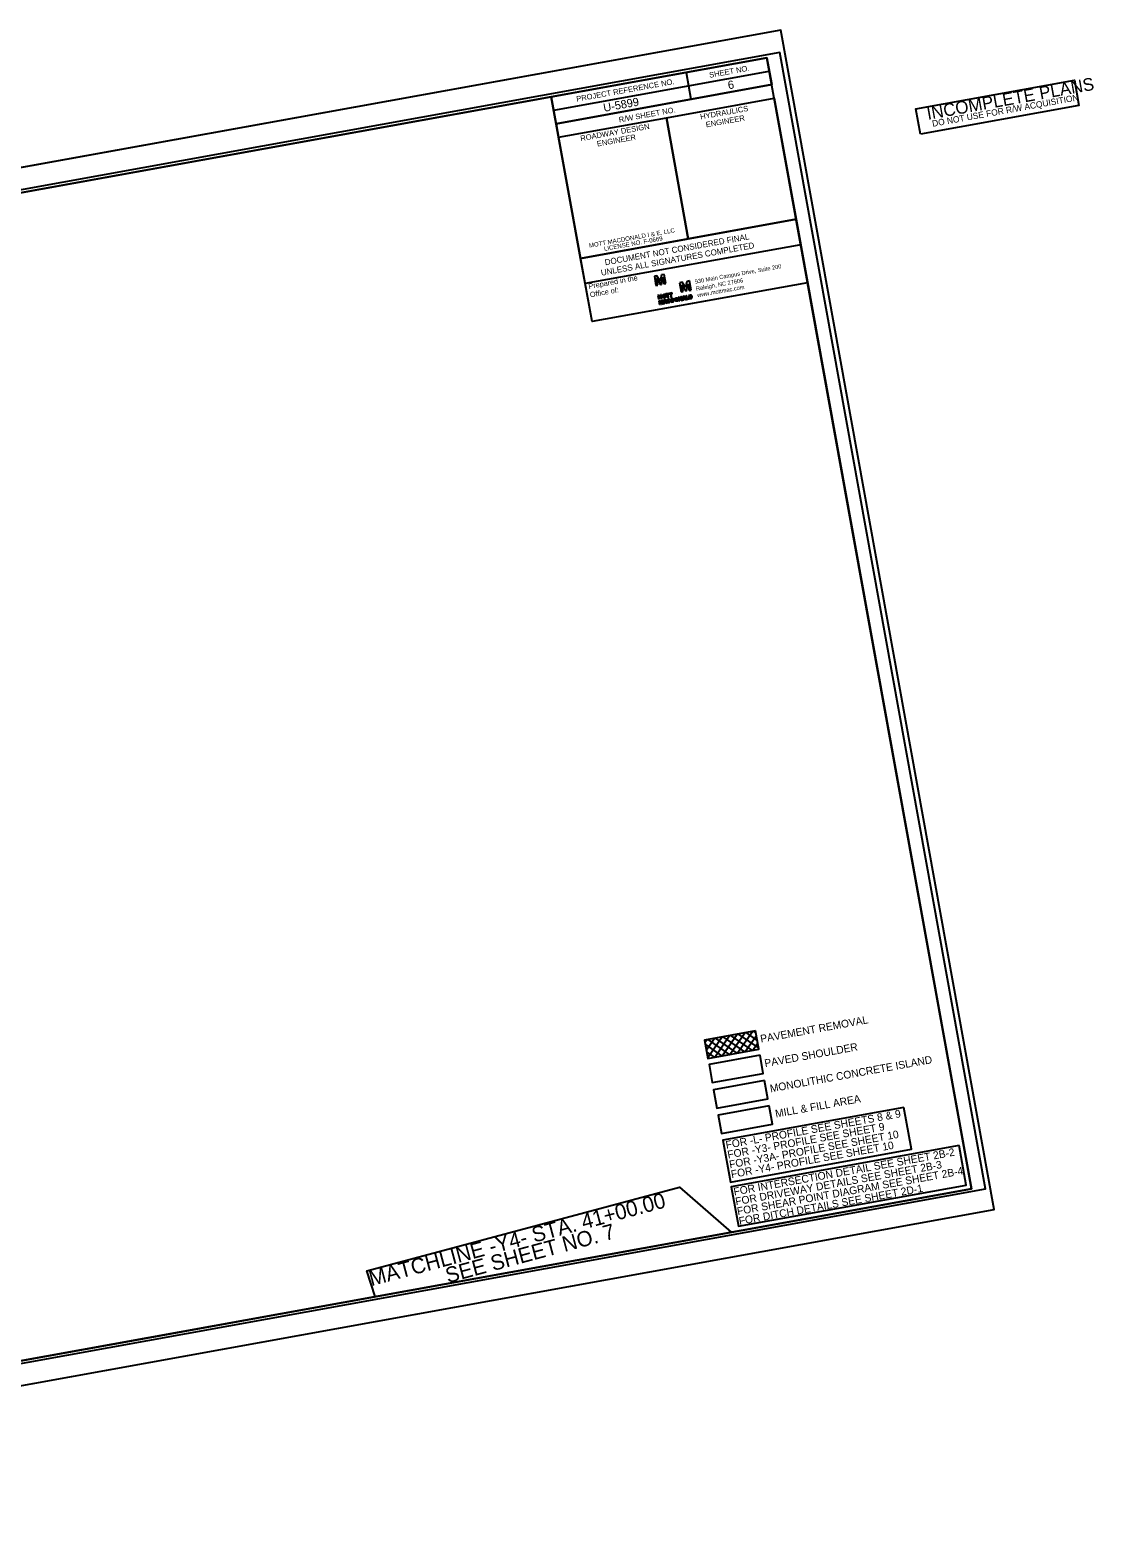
# Model space of a CAD drawing. Extents: x 1620188 to 1622130, y 897586 to 898964.
# Drawn here: x 1621159 to 1622130, y 897586 to 898964 of the extents above; entities that cross this region are included whole.
import ezdxf

# ---------------------------------------------------------------- set-up
doc = ezdxf.new("R2010")
doc.units = 0
for name, color, linetype in [('Matchline', 7, 'Continuous'), ('Matchline Text', 7, 'Continuous'), ('Old_Level_2', 7, 'Continuous'), ('Old_Level_40', 7, 'Continuous'), ('Old_Level_42', 7, 'Continuous'), ('Old_Level_45', 7, 'Continuous'), ('Prop DSN Text', 7, 'Continuous'), ('Prop Rem of Exist Asph Pvmt', 7, 'Continuous'), ('Prop Shade Light', 7, 'Continuous'), ('Sheet Cutting Line CELL', 7, 'Continuous'), ('Sheet Data Field CELL', 7, 'Continuous'), ('Sheet Layout Plan Border', 7, 'Continuous'), ('Sheet Plan CELL', 7, 'Continuous'), ('Sheet Plot Border Inside CELL', 7, 'Continuous'), ('Sheet Plot Border Outside CELL', 7, 'Continuous'), ('Sheet Sticker Exception Certification CELL', 7, 'Continuous'), ('Sheet Sticker Incomplete CELL', 7, 'Continuous')]:
    doc.layers.add(name, color=color, linetype=linetype)

msp = doc.modelspace()

# ---------------------------------------------------------------- linework, layer by layer
at = {"layer": 'Matchline'}
msp.add_line((1621466.5, 897830.2), (1621752, 897906.6), dxfattribs=at)
at = {"layer": 'Old_Level_2'}
for p, q in [((1621731.5, 898739.3), (1621729.1, 898738.9)), ((1621729.1, 898738.9), (1621730.6, 898730.5)), ((1621731.2, 898736.8), (1621731.3, 898736.9)), ((1621732.3, 898730.8), (1621731.2, 898736.8)), ((1621731.3, 898736.9), (1621734.7, 898731.3)), ((1621734.5, 898734.5), (1621731.5, 898739.3)), ((1621735.6, 898740.1), (1621734.5, 898734.5)), ((1621734.5, 898734.5), (1621734.6, 898734.5)), ((1621734.6, 898734.5), (1621734.5, 898734.4)), ((1621734.5, 898734.4), (1621734.5, 898734.5)), ((1621735.5, 898731.4), (1621736.7, 898737.9)), ((1621738.1, 898740.5), (1621735.6, 898740.1)), ((1621736.7, 898737.9), (1621736.8, 898737.9)), ((1621736.8, 898737.9), (1621737.9, 898731.8)), ((1621739.6, 898732.2), (1621738.1, 898740.5)), ((1621754.6, 898733.4), (1621752.1, 898733)), ((1621752.1, 898733), (1621753.6, 898724.6)), ((1621757.5, 898728.6), (1621754.6, 898733.4)), ((1621758.7, 898734.2), (1621757.6, 898728.6)), ((1621761.1, 898734.6), (1621758.7, 898734.2)), ((1621762.7, 898726.3), (1621761.1, 898734.6)), ((1621730.6, 898730.5), (1621732.3, 898730.8)), ((1621733.2, 898721.5), (1621732.2, 898721.4)), ((1621732.2, 898721.4), (1621732.8, 898718.2)), ((1621733.5, 898718.3), (1621733.1, 898720.6)), ((1621733.1, 898720.6), (1621733.1, 898720.6)), ((1621733.1, 898720.6), (1621734.4, 898718.4)), ((1621734.3, 898719.7), (1621733.2, 898721.5)), ((1621734.8, 898721.8), (1621734.3, 898719.7)), ((1621734.7, 898731.3), (1621735.5, 898731.4)), ((1621734.7, 898718.5), (1621735.2, 898721)), ((1621735.7, 898722), (1621734.8, 898721.8)), ((1621735.2, 898721), (1621735.2, 898721)), ((1621735.2, 898721), (1621735.6, 898718.7)), ((1621735.6, 898718.7), (1621736.3, 898718.8)), ((1621736.3, 898718.8), (1621735.7, 898722)), ((1621737.9, 898731.8), (1621739.6, 898732.2)), ((1621745.3, 898718.6), (1621743.8, 898718.3)), ((1621745.9, 898722.9), (1621746, 898722.9)), ((1621748, 898723.3), (1621748.1, 898723.3)), ((1621748, 898723.3), (1621748.1, 898723.3)), ((1621753.6, 898724.6), (1621755.4, 898724.9)), ((1621754.3, 898730.9), (1621754.3, 898731)), ((1621754.3, 898731), (1621757.7, 898725.4)), ((1621755.4, 898724.9), (1621754.3, 898730.9)), ((1621757.6, 898728.6), (1621757.5, 898728.6)), ((1621757.5, 898728.6), (1621757.5, 898728.6)), ((1621757.6, 898728.6), (1621757.6, 898728.6)), ((1621757.7, 898725.4), (1621758.5, 898725.5)), ((1621758.5, 898725.5), (1621759.8, 898732)), ((1621759.8, 898732), (1621759.8, 898732)), ((1621759.8, 898732), (1621760.9, 898725.9)), ((1621761.9, 898721.6), (1621760.4, 898721.3)), ((1621760.4, 898721.3), (1621760.4, 898721.3)), ((1621760.4, 898721.3), (1621760.7, 898719.7)), ((1621760.7, 898719.7), (1621761, 898718.1)), ((1621760.9, 898725.9), (1621762.7, 898726.3)), ((1621761.2, 898720.9), (1621762, 898721)), ((1621761.5, 898718.9), (1621761.2, 898720.9)), ((1621762.3, 898719), (1621761.5, 898718.9)), ((1621762, 898721), (1621762, 898721)), ((1621732.8, 898718.2), (1621733.5, 898718.3)), ((1621734.1, 898716.6), (1621733.1, 898716.4)), ((1621733.1, 898716.4), (1621733.7, 898713.2)), ((1621733.7, 898713.2), (1621734.4, 898713.3)), ((1621734.4, 898713.3), (1621734, 898715.6)), ((1621734, 898715.6), (1621734, 898715.6)), ((1621734, 898715.6), (1621735.3, 898713.5)), ((1621735.2, 898714.7), (1621734.1, 898716.6)), ((1621734.4, 898718.4), (1621734.7, 898718.5)), ((1621735.7, 898716.9), (1621735.2, 898714.7)), ((1621735.3, 898713.5), (1621735.6, 898713.5)), ((1621735.6, 898713.5), (1621736.1, 898716)), ((1621736.6, 898717), (1621735.7, 898716.9)), ((1621736.1, 898716), (1621736.1, 898716)), ((1621736.1, 898716), (1621736.5, 898713.7)), ((1621736.5, 898713.7), (1621737.2, 898713.8)), ((1621737.2, 898713.8), (1621736.6, 898717)), ((1621743, 898717.1), (1621743.5, 898717.5)), ((1621743.8, 898715.7), (1621743.2, 898715.9)), ((1621743.8, 898718.3), (1621744.1, 898716.7)), ((1621744.1, 898716.7), (1621744.4, 898715.1)), ((1621744.4, 898715.1), (1621745.9, 898715.4)), ((1621744.6, 898717.9), (1621745.4, 898718)), ((1621745, 898715.9), (1621744.6, 898717.9)), ((1621745.8, 898716), (1621745, 898715.9)), ((1621761, 898718.1), (1621762.4, 898718.4))]:
    msp.add_line(p, q, dxfattribs=at)
for points in [[(1621739.8, 898722.1), (1621740.7, 898722.3), (1621741.2, 898719.7), (1621741.9, 898719.8), (1621741.4, 898722.4), (1621742.4, 898722.6), (1621742.3, 898723.2), (1621739.7, 898722.7), (1621739.8, 898722.1)], [(1621742.8, 898722.7), (1621743.7, 898722.8), (1621744.2, 898720.2), (1621744.9, 898720.3), (1621744.4, 898722.9), (1621745.3, 898723.1), (1621745.2, 898723.7), (1621742.7, 898723.2), (1621742.8, 898722.7)], [(1621751.9, 898718.6), (1621751.9, 898718.6), (1621753.8, 898716.8), (1621754.4, 898717), (1621753.9, 898720.1), (1621753.2, 898720), (1621753.6, 898718), (1621751.7, 898719.8), (1621751, 898719.6), (1621751.6, 898716.4), (1621752.2, 898716.6), (1621751.9, 898718.6)], [(1621754.9, 898717), (1621755.6, 898717.2), (1621755.7, 898717.7), (1621757.1, 898718), (1621757.4, 898717.5), (1621758.2, 898717.6), (1621756.3, 898720.6), (1621755.5, 898720.4), (1621754.9, 898717)], [(1621755.8, 898718.4), (1621756.1, 898719.8), (1621756.8, 898718.5), (1621755.8, 898718.4)], [(1621760.6, 898718.1), (1621760.5, 898718.6), (1621759.1, 898718.4), (1621758.6, 898721), (1621758, 898720.9), (1621758.5, 898717.7), (1621760.6, 898718.1)], [(1621737.6, 898713.9), (1621738.3, 898714), (1621738.4, 898714.6), (1621739.8, 898714.9), (1621740.1, 898714.4), (1621740.9, 898714.5), (1621739.1, 898717.5), (1621738.2, 898717.3), (1621737.6, 898713.9)], [(1621738.5, 898715.2), (1621738.8, 898716.7), (1621739.5, 898715.4), (1621738.5, 898715.2)]]:
    msp.add_lwpolyline(points, dxfattribs=at)
msp.add_arc((1621762.1, 898720), 1.62, 280.2583, 100.2583, dxfattribs=at)
for centre, major_axis, ratio in [((1621738.2, 898720.8), (-0.29, 1.6), 0.993118), ((1621738.2, 898720.8), (-0.19, 1.04), 0.916103), ((1621749.2, 898717.6), (-0.29, 1.6), 0.993118), ((1621749.2, 898717.6), (-0.19, 1.04), 0.916103)]:
    msp.add_ellipse(centre, major_axis=major_axis, ratio=ratio, dxfattribs=at)
for centre, major_axis, ratio, start_param, end_param in [((1621745.6, 898717), (0.29, -1.6), 0.930276, 0, 3.141593), ((1621762.1, 898720), (0.181, -0.998), 0.900832, 0, 3.141593), ((1621742.3, 898716.4), (-0.29, 1.6), 0.993118, 5.246647, 10.366427), ((1621742.3, 898716.4), (-0.19, 1.04), 0.916103, 5.276876, 10.296021), ((1621745.6, 898717), (0.181, -0.998), 0.900832, 0, 3.141593)]:
    msp.add_ellipse(centre, major_axis=major_axis, ratio=ratio, start_param=start_param, end_param=end_param, dxfattribs=at)
at = {"layer": 'Old_Level_40'}
for points in [[(1621821.6, 898049.5), (1621775, 898041.1), (1621778, 898024.4), (1621824.6, 898032.8)], [(1621825.6, 898027.3), (1621779, 898018.8), (1621782, 898002.2), (1621828.6, 898010.6)], [(1621829.8, 898004.1), (1621783.2, 897995.7), (1621786.2, 897979), (1621832.8, 897987.4)], [(1621834, 897980.9), (1621787.4, 897972.5), (1621790.4, 897955.8), (1621837, 897964.2)], [(1621957, 897979.5), (1621791.6, 897949.6), (1621798.5, 897911.3), (1621963.9, 897941.3)], [(1622007.4, 897944.8), (1621799.2, 897907.1), (1621805.8, 897871), (1622013.9, 897908.7)]]:
    msp.add_lwpolyline(points, close=True, dxfattribs=at)
at = {"layer": 'Old_Level_42'}
msp.add_lwpolyline([(1621869, 898733), (1621672.2, 898697.4), (1621665.9, 898732.1)], dxfattribs=at)
at = {"layer": 'Prop Rem of Exist Asph Pvmt'}
for p, q in [((1621777.9, 898025.2), (1621790.8, 898043.9)), ((1621784.2, 898025.5), (1621797.8, 898045.2)), ((1621791.1, 898026.8), (1621804.8, 898046.5)), ((1621791.7, 898044.1), (1621811.4, 898030.4)), ((1621798.1, 898028), (1621811.7, 898047.7)), ((1621798.7, 898045.4), (1621818.4, 898031.7)), ((1621805, 898029.3), (1621818.7, 898049)), ((1621805.6, 898046.6), (1621824.4, 898033.6)), ((1621812, 898030.6), (1621822.3, 898045.4)), ((1621812.6, 898047.9), (1621823.2, 898040.5)), ((1621819.5, 898049.1), (1621821.9, 898047.5)), ((1621775.3, 898039.1), (1621776.9, 898041.4)), ((1621775.7, 898036.9), (1621790.5, 898026.7)), ((1621776.6, 898032.2), (1621783.9, 898042.7)), ((1621777, 898030), (1621783.6, 898025.4)), ((1621777.8, 898041.6), (1621797.5, 898027.9)), ((1621784.7, 898042.8), (1621804.4, 898029.2)), ((1621818.9, 898031.8), (1621823.6, 898038.5))]:
    msp.add_line(p, q, dxfattribs=at)
at = {"layer": 'Prop Shade Light'}
for points in [[(1621825.6, 898027.3), (1621779, 898018.8), (1621782, 898002.2), (1621828.6, 898010.6), (1621825.6, 898027.3)], [(1621829.8, 898004.1), (1621783.2, 897995.7), (1621786.2, 897979), (1621832.8, 897987.4), (1621829.8, 898004.1)], [(1621834, 897980.9), (1621787.4, 897972.5), (1621790.4, 897955.8), (1621837, 897964.2), (1621834, 897980.9)]]:
    msp.add_lwpolyline(points, dxfattribs=at)
at = {"layer": 'Sheet Cutting Line CELL'}
for p, q in [((1621844.5, 898963.7), (1620187.9, 898663.9)), ((1620382.9, 897586.4), (1622039.5, 897886.2))]:
    msp.add_line(p, q, dxfattribs=at)
at = {"layer": 'Sheet Layout Plan Border'}
msp.add_lwpolyline([(1620396.1, 898448.3), (1620511.7, 898448.3), (1620511.8, 898225.2), (1620537.8, 897924.1), (1620549.3, 897792), (1620711.8, 897792), (1620711.8, 897668.8), (1621290.7, 897773.5), (1621387.6, 897791.1), (1621474.2, 897806.7), (1621466.5, 897830.2), (1621752, 897906.6), (1621799.3, 897865.6), (1622018.8, 897905.3), (1621899.5, 898564.6), (1621869, 898733), (1621765.3, 898714.2), (1621672.2, 898697.4), (1621635, 898902.9), (1620355.8, 898671.4)], close=True, dxfattribs=at)
at = {"layer": 'Sheet Plan CELL'}
for p, q in [((1621637.2, 898890.6), (1621834, 898926.2)), ((1621639.4, 898878.2), (1621836.3, 898913.9)), ((1621639.4, 898878.2), (1621836.3, 898913.9)), ((1621758, 898925.1), (1621762.5, 898900.5)), ((1621639.4, 898878.2), (1621641.6, 898865.9)), ((1621740.1, 898883.7), (1621760.1, 898773.1))]:
    msp.add_line(p, q, dxfattribs=at)
for points in [[(1621831.8, 898938.5), (1620355.8, 898671.4), (1620542.8, 897638.2), (1622018.8, 897905.3)], [(1621634.9, 898902.9), (1621831.8, 898938.5), (1621836.3, 898913.9), (1621639.4, 898878.2)], [(1620542.8, 897638.2), (1620355.7, 898671.4), (1621634.9, 898902.9), (1621661.7, 898755.2), (1621858.5, 898790.9), (1622018.8, 897905.3)], [(1621740.1, 898883.7), (1621838.5, 898901.6), (1621858.5, 898790.9), (1621760.1, 898773)], [(1621641.6, 898865.9), (1621740.1, 898883.7), (1621760.1, 898773), (1621661.7, 898755.2)]]:
    msp.add_lwpolyline(points, close=True, dxfattribs=at)
at = {"layer": 'Sheet Plot Border Inside CELL'}
msp.add_lwpolyline([(1620392.2, 897608.4), (1622031.5, 897905.1), (1621843.7, 898943.2), (1620204.3, 898646.5)], close=True, dxfattribs=at)
at = {"layer": 'Sheet Plot Border Outside CELL'}
msp.add_lwpolyline([(1620382.9, 897586.4), (1622039.5, 897886.2), (1621844.5, 898963.7), (1620187.9, 898663.9)], close=True, dxfattribs=at)
at = {"layer": 'Sheet Sticker Exception Certification CELL'}
for p, q in [((1621661.7, 898755.2), (1621858.5, 898790.9)), ((1621858.5, 898790.9), (1621862.7, 898767.7)), ((1621862.7, 898767.7), (1621665.9, 898732.1)), ((1621665.9, 898732.1), (1621661.7, 898755.2))]:
    msp.add_line(p, q, dxfattribs=at)
at = {"layer": 'Sheet Sticker Incomplete CELL'}
msp.add_lwpolyline([(1621972.2, 898868.6), (1621968, 898891.7), (1622112.6, 898917.9), (1622116.8, 898894.8)], close=True, dxfattribs=at)

# ---------------------------------------------------------------- texts
at = {"layer": 'Matchline Text'}
for s, p in [('MATCHLINE -Y4- STA. 41+00.00', (1621470.6, 897816.2)), ('SEE SHEET NO. 7', (1621540.5, 897819))]:
    msp.add_text(s, height=14, rotation=14.985, dxfattribs=at).set_placement(p)
at = {"layer": 'Old_Level_2'}
for s, height, p in [('930 Main Campus Drive, Suite 200', 3.75, (1621766.3, 898732)), ('Prepared in the ', 4.819, (1621669.4, 898727.2)), ('Raleigh, NC 27606', 3.75, (1621767.4, 898725.6)), ('Office of:', 4.82, (1621670.7, 898719.5)), ('www.mottmac.com', 3.75, (1621768.5, 898719.6))]:
    msp.add_text(s, height=height, rotation=10.2583, dxfattribs=at).set_placement(p)
at = {"layer": 'Old_Level_45'}
for s, p in [('MOTT MACDONALD I & E, LLC', (1621669.8, 898764.9)), (' LICENSE NO. F-0669', (1621682, 898761.7))]:
    msp.add_text(s, height=4.018, rotation=10.2583, dxfattribs=at).set_placement(p)
at = {"layer": 'Prop DSN Text'}
for s, p in [('PAVEMENT REMOVAL', (1621826.5, 898038.7)), ('PAVED SHOULDER', (1621830.3, 898016.4)), ('MONOLITHIC CONCRETE ISLAND', (1621835.3, 897993.3)), ('MILL & FILL AREA', (1621840.1, 897970.3)), ('FOR -L- PROFILE SEE SHEETS 8 & 9', (1621794.9, 897941.8)), ('FOR -Y3- PROFILE SEE SHEET 9', (1621796.5, 897932.9)), ('FOR -Y3A- PROFILE SEE SHEET 10', (1621798.1, 897923.9)), ('FOR -Y4- PROFILE SEE SHEET 10', (1621799.7, 897915)), ('FOR INTERSECTION DETAIL SEE SHEET 2B-2', (1621802.1, 897899.1)), ('FOR DRIVEWAY DETAILS SEE SHEET 2B-3', (1621803.7, 897890.1)), ('FOR SHEAR POINT DIAGRAM SEE SHEET 2B-4', (1621805.3, 897881.2)), ('FOR DITCH DETAILS SEE SHEET 2D-1', (1621806.9, 897872.2))]:
    msp.add_text(s, height=7, rotation=10.2583, dxfattribs=at).set_placement(p)
at = {"layer": 'Sheet Data Field CELL'}
for s, p in [('6', (1621796.9, 898909.6)), ('U-5899', (1621683.2, 898889))]:
    msp.add_text(s, height=7.5, rotation=10.2583, dxfattribs=at).set_placement(p)
at = {"layer": 'Sheet Plan CELL'}
for s, p in [('SHEET NO.', (1621779.6, 898920.1)), ('PROJECT REFERENCE NO.', (1621658.3, 898898.3)), ('R/W SHEET NO.', (1621697.1, 898879.3)), ('HYDRAULICS', (1621771.4, 898882)), ('ENGINEER', (1621776.5, 898874.8)), ('ROADWAY DESIGN', (1621662, 898862.2)), ('ENGINEER', (1621677.1, 898857.3))]:
    msp.add_text(s, height=5, rotation=10.2583, dxfattribs=at).set_placement(p)
at = {"layer": 'Sheet Sticker Exception Certification CELL'}
for s, p in [('DOCUMENT NOT CONSIDERED FINAL', (1621684.3, 898748.8)), ('UNLESS ALL SIGNATURES COMPLETED', (1621680.8, 898739.3))]:
    msp.add_text(s, height=5.5, rotation=10.2583, dxfattribs=at).set_placement(p)
at = {"layer": 'Sheet Sticker Incomplete CELL'}
for s, height, p in [('INCOMPLETE PLANS', 11.52, (1621978.9, 898881.7)), ('DO NOT USE FOR R/W ACQUISITION', 5.76, (1621983.3, 898875.4))]:
    msp.add_text(s, height=height, rotation=10.2583, dxfattribs=at).set_placement(p)

doc.saveas('drawing.dxf')
